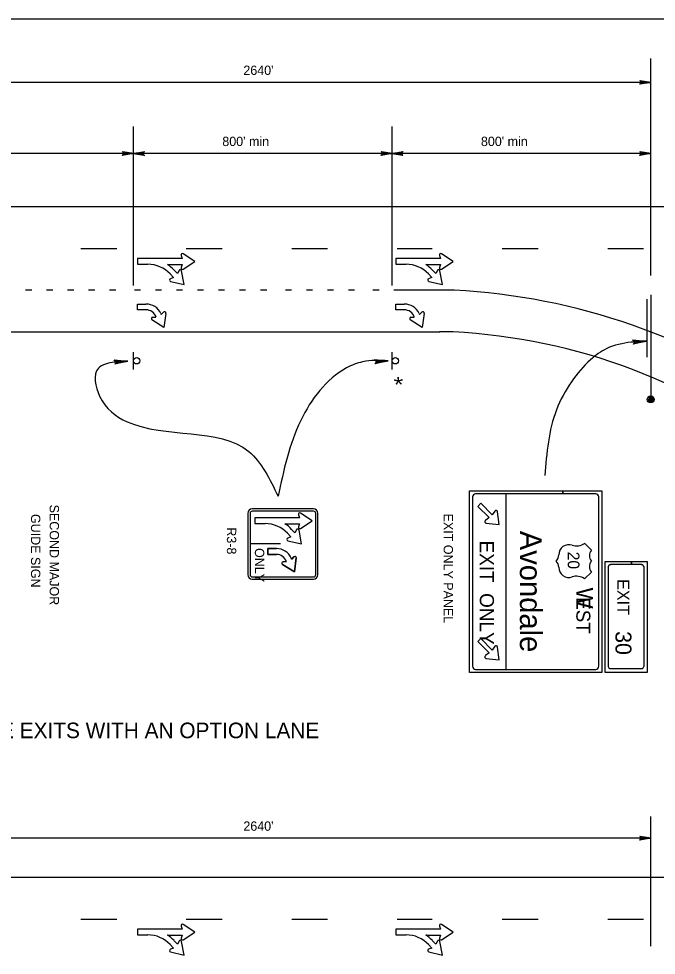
# Model space of a CAD drawing. Extents: x 644898 to 648326, y 298294 to 300670.
# Drawn here: x 645333.7 to 645538.5, y 298572.7 to 298873.5 of the extents above; entities that cross this region are included whole.
import ezdxf

# ---------------------------------------------------------------- set-up
doc = ezdxf.new("R2010")
doc.units = 0
doc.layers.add('1', color=7, linetype='Continuous')
doc.layers.add('2', color=7, linetype='Continuous')

msp = doc.modelspace()

# ---------------------------------------------------------------- linework, layer by layer
at = {"layer": '1'}
msp.add_line((644938.32, 298873.49), (645724.32, 298873.49), dxfattribs=at)
at = {"layer": '2'}
for p, q in [((645536.72, 298791.02), (645536.72, 298860.69)), ((645533.35, 298853.56), (645533.22, 298853.69)), ((645533.22, 298853.69), (645536.72, 298853.06)), ((645533.35, 298853.56), (645533.47, 298853.31)), ((645536.72, 298853.06), (645533.35, 298853.56)), ((645536.72, 298853.06), (645287.45, 298853.06)), ((645536.72, 298853.06), (645533.22, 298852.44)), ((645533.22, 298852.44), (645533.35, 298852.69)), ((645533.35, 298852.69), (645536.72, 298853.06)), ((645533.47, 298852.94), (645533.35, 298852.69)), ((645533.47, 298853.31), (645536.72, 298853.06)), ((645536.72, 298853.06), (645533.47, 298852.94)), ((645370.54, 298787.81), (645370.54, 298838.91)), ((645453.63, 298787.81), (645453.63, 298838.91)), ((645370.54, 298830.22), (645287.45, 298830.22)), ((645367.17, 298830.72), (645367.04, 298830.85)), ((645367.04, 298830.85), (645370.54, 298830.22)), ((645370.54, 298830.22), (645367.04, 298829.6)), ((645367.04, 298829.6), (645367.17, 298829.85)), ((645367.17, 298830.72), (645367.29, 298830.47)), ((645370.54, 298830.22), (645367.17, 298830.72)), ((645367.17, 298829.85), (645370.54, 298830.22)), ((645367.29, 298830.1), (645367.17, 298829.85)), ((645367.29, 298830.47), (645370.54, 298830.22)), ((645370.54, 298830.22), (645367.29, 298830.1)), ((645370.54, 298830.22), (645374.04, 298830.85)), ((645373.92, 298830.6), (645370.54, 298830.22)), ((645370.54, 298830.22), (645373.79, 298830.35)), ((645453.63, 298830.22), (645370.54, 298830.22)), ((645373.79, 298829.97), (645370.54, 298830.22)), ((645370.54, 298830.22), (645373.92, 298829.72)), ((645374.04, 298829.6), (645370.54, 298830.22)), ((645373.79, 298830.35), (645373.92, 298830.6)), ((645373.92, 298829.72), (645373.79, 298829.97)), ((645374.04, 298830.85), (645373.92, 298830.6)), ((645373.92, 298829.72), (645374.04, 298829.6)), ((645450.26, 298830.72), (645450.13, 298830.85)), ((645450.13, 298830.85), (645453.63, 298830.22)), ((645453.63, 298830.22), (645450.13, 298829.6)), ((645450.13, 298829.6), (645450.26, 298829.85)), ((645450.26, 298830.72), (645450.38, 298830.47)), ((645453.63, 298830.22), (645450.26, 298830.72)), ((645450.26, 298829.85), (645453.63, 298830.22)), ((645450.38, 298830.1), (645450.26, 298829.85)), ((645450.38, 298830.47), (645453.63, 298830.22)), ((645453.63, 298830.22), (645450.38, 298830.1)), ((645453.63, 298830.22), (645457.13, 298830.85)), ((645457.01, 298830.6), (645453.63, 298830.22)), ((645453.63, 298830.22), (645456.88, 298830.35)), ((645536.72, 298830.22), (645453.63, 298830.22)), ((645456.88, 298829.97), (645453.63, 298830.22)), ((645453.63, 298830.22), (645457.01, 298829.72)), ((645457.13, 298829.6), (645453.63, 298830.22)), ((645456.88, 298830.35), (645457.01, 298830.6)), ((645457.01, 298829.72), (645456.88, 298829.97)), ((645457.13, 298830.85), (645457.01, 298830.6)), ((645457.01, 298829.72), (645457.13, 298829.6)), ((645533.35, 298830.72), (645533.22, 298830.85)), ((645533.22, 298830.85), (645536.72, 298830.22)), ((645536.72, 298830.22), (645533.22, 298829.6)), ((645533.22, 298829.6), (645533.35, 298829.85)), ((645533.35, 298830.72), (645533.47, 298830.47)), ((645536.72, 298830.22), (645533.35, 298830.72)), ((645533.35, 298829.85), (645536.72, 298830.22)), ((645533.47, 298830.1), (645533.35, 298829.85)), ((645533.47, 298830.47), (645536.72, 298830.22)), ((645536.72, 298830.22), (645533.47, 298830.1)), ((645010.69, 298813.15), (645651.96, 298813.15)), ((645353.66, 298799.69), (645365.16, 298799.69)), ((645387.53, 298799.69), (645399.03, 298799.69)), ((645421.41, 298799.69), (645432.91, 298799.69)), ((645455.28, 298799.69), (645466.53, 298799.69)), ((645489.03, 298799.69), (645500.53, 298799.69)), ((645522.91, 298799.69), (645534.41, 298799.69)), ((645386.24, 298796.46), (645371.85, 298796.46)), ((645371.85, 298796.46), (645371.85, 298794.63)), ((645385.85, 298797.44), (645386.24, 298796.46)), ((645390.3, 298795.53), (645386.51, 298797.99)), ((645469.23, 298796.46), (645454.84, 298796.46)), ((645454.84, 298796.46), (645454.84, 298794.63)), ((645468.84, 298797.44), (645469.23, 298796.46)), ((645473.29, 298795.53), (645469.5, 298797.99)), ((645371.85, 298794.63), (645375.15, 298794.63)), ((645381.45, 298794.59), (645386.24, 298794.59)), ((645386.24, 298794.59), (645385.85, 298793.61)), ((645386.51, 298793.07), (645390.3, 298795.53)), ((645454.84, 298794.63), (645458.14, 298794.63)), ((645464.43, 298794.59), (645469.23, 298794.59)), ((645469.23, 298794.59), (645468.84, 298793.61)), ((645469.5, 298793.07), (645473.29, 298795.53)), ((645382.34, 298791.53), (645383.41, 298790.4)), ((645383.41, 298790.4), (645382.4, 298789.99)), ((645384.72, 298791.63), (645383.65, 298792.77)), ((645385.18, 298792.63), (645384.72, 298791.63)), ((645386.85, 298788.08), (645386.03, 298792.52)), ((645465.33, 298791.53), (645466.4, 298790.4)), ((645466.4, 298790.4), (645465.38, 298789.99)), ((645467.71, 298791.63), (645466.63, 298792.77)), ((645468.17, 298792.63), (645467.71, 298791.63)), ((645469.84, 298788.08), (645469.02, 298792.52)), ((645382.46, 298789.14), (645386.85, 298788.08)), ((645465.45, 298789.14), (645469.84, 298788.08)), ((645337.85, 298786.27), (645335.85, 298786.27)), ((645344.6, 298786.27), (645342.6, 298786.27)), ((645351.35, 298786.27), (645349.35, 298786.27)), ((645358.1, 298786.27), (645356.1, 298786.27)), ((645364.85, 298786.27), (645362.85, 298786.27)), ((645372.84, 298786.27), (645370.84, 298786.27)), ((645379.59, 298786.27), (645377.59, 298786.27)), ((645386.34, 298786.27), (645384.34, 298786.27)), ((645393.09, 298786.27), (645391.09, 298786.27)), ((645399.84, 298786.27), (645397.84, 298786.27)), ((645406.59, 298786.27), (645404.59, 298786.27)), ((645413.34, 298786.27), (645411.34, 298786.27)), ((645421.34, 298786.27), (645419.34, 298786.27)), ((645428.09, 298786.27), (645426.09, 298786.27)), ((645434.84, 298786.27), (645432.84, 298786.27)), ((645441.59, 298786.27), (645439.59, 298786.27)), ((645449.45, 298786.27), (645447.45, 298786.27)), ((645473.61, 298786.27), (645454.2, 298786.27)), ((645536.72, 298784.86), (645536.72, 298751.17)), ((645535.6, 298764.78), (645535.6, 298783.37)), ((645010.69, 298772.9), (645442.59, 298772.9)), ((645442.59, 298772.9), (645454.2, 298772.9)), ((645454.2, 298772.9), (645468.92, 298772.9)), ((645370.54, 298760.83), (645370.54, 298766.45)), ((645453.63, 298760.83), (645453.63, 298766.45)), ((645537.47, 298751.42), (645535.85, 298751.04)), ((645536.6, 298750.42), (645535.85, 298751.29)), ((645535.85, 298751.29), (645537.22, 298750.42)), ((645537.22, 298751.92), (645535.97, 298751.54)), ((645535.97, 298751.54), (645537.47, 298751.42)), ((645536.1, 298751.92), (645537.22, 298751.92)), ((645537.22, 298750.42), (645536.6, 298752.17)), ((645536.6, 298752.17), (645537.72, 298751.04)), ((645537.72, 298751.04), (645537.22, 298752.04)), ((645535.85, 298751.04), (645537.72, 298751.04)), ((645537.72, 298751.04), (645535.97, 298750.67)), ((645535.97, 298750.67), (645537.47, 298750.67)), ((645537.47, 298750.67), (645536.6, 298750.42)), ((645536.72, 298751.17), (645536.72, 298751.17)), ((645478.45, 298663.53), (645478.45, 298721.9)), ((645478.45, 298721.9), (645508.47, 298721.9)), ((645508.47, 298720.9), (645508.47, 298721.9)), ((645508.47, 298721.9), (645521.07, 298721.9)), ((645508.47, 298721.9), (645508.47, 298720.9)), ((645521.07, 298721.9), (645521.07, 298663.53)), ((645479.45, 298719.9), (645479.45, 298665.53)), ((645520.07, 298665.53), (645520.07, 298719.9)), ((645482.18, 298717.88), (645481.18, 298716.88)), ((645481.18, 298716.88), (645484.8, 298713.25)), ((645485.8, 298714.19), (645482.18, 298717.88)), ((645486.61, 298715.38), (645485.8, 298714.19)), ((645423.94, 298713.18), (645409.55, 298713.18)), ((645409.55, 298713.18), (645409.55, 298711.34)), ((645423.55, 298714.16), (645423.94, 298713.18)), ((645428, 298712.24), (645424.21, 298714.7)), ((645424.21, 298709.78), (645428, 298712.24)), ((645484.8, 298713.25), (645483.61, 298712.38)), ((645488.05, 298711), (645487.55, 298715.13)), ((645409.55, 298711.34), (645412.85, 298711.34)), ((645419.14, 298711.3), (645423.94, 298711.3)), ((645422.42, 298708.35), (645421.35, 298709.48)), ((645422.88, 298709.34), (645422.42, 298708.35)), ((645423.94, 298711.3), (645423.55, 298710.32)), ((645424.55, 298704.79), (645423.73, 298709.23)), ((645483.8, 298711.5), (645488.05, 298711)), ((645420.04, 298708.24), (645421.11, 298707.11)), ((645421.11, 298707.11), (645420.1, 298706.7)), ((645420.16, 298705.85), (645424.55, 298704.79)), ((645515.45, 298705.06), (645517.7, 298702.81)), ((645507.2, 298701.31), (645507.2, 298701.31)), ((645507.2, 298697.31), (645507.2, 298697.31)), ((645511.95, 298699.31), (645511.95, 298699.31)), ((645511.95, 298699.31), (645511.95, 298699.31)), ((645511.95, 298699.31), (645511.95, 298699.31)), ((645511.95, 298699.31), (645511.95, 298699.31)), ((645511.95, 298699.31), (645511.95, 298699.31)), ((645511.95, 298699.31), (645511.95, 298699.31)), ((645522.07, 298663.53), (645522.07, 298699.15)), ((645522.07, 298699.15), (645530.53, 298699.15)), ((645523.07, 298697.53), (645523.07, 298665.4)), ((645530.53, 298698.15), (645523.82, 298698.15)), ((645530.53, 298698.15), (645530.53, 298699.15)), ((645530.53, 298699.15), (645535.57, 298699.15)), ((645530.53, 298699.15), (645530.53, 298698.15)), ((645533.82, 298698.15), (645530.53, 298698.15)), ((645534.57, 298665.4), (645534.57, 298697.53)), ((645535.57, 298699.15), (645535.57, 298663.53)), ((645509.7, 298697.06), (645509.7, 298697.06)), ((645517.7, 298695.69), (645515.45, 298693.56)), ((645510.45, 298694.06), (645510.45, 298694.06)), ((645482.18, 298674.43), (645481.18, 298673.43)), ((645481.18, 298673.43), (645484.8, 298669.8)), ((645485.8, 298670.74), (645482.18, 298674.43)), ((645486.61, 298671.93), (645485.8, 298670.74)), ((645488.05, 298667.55), (645487.55, 298671.68)), ((645484.8, 298669.8), (645483.61, 298668.93)), ((645483.8, 298668.05), (645488.05, 298667.55)), ((645480.45, 298664.53), (645519.07, 298664.53)), ((645523.82, 298664.78), (645533.82, 298664.78)), ((645521.07, 298663.53), (645478.45, 298663.53)), ((645535.57, 298663.53), (645522.07, 298663.53)), ((645536.72, 298575.63), (645536.72, 298617.3)), ((645536.72, 298610.3), (645287.45, 298610.3)), ((645533.35, 298610.8), (645533.22, 298610.93)), ((645533.22, 298610.93), (645536.72, 298610.3)), ((645536.72, 298610.3), (645533.22, 298609.68)), ((645533.22, 298609.68), (645533.35, 298609.93)), ((645533.35, 298610.8), (645533.47, 298610.55)), ((645536.72, 298610.3), (645533.35, 298610.8)), ((645533.35, 298609.93), (645536.72, 298610.3)), ((645533.47, 298610.18), (645533.35, 298609.93)), ((645533.47, 298610.55), (645536.72, 298610.3)), ((645536.72, 298610.3), (645533.47, 298610.18)), ((645010.69, 298597.76), (645651.96, 298597.76)), ((645353.66, 298584.3), (645365.16, 298584.3)), ((645387.53, 298584.3), (645399.03, 298584.3)), ((645421.41, 298584.3), (645432.91, 298584.3)), ((645455.28, 298584.3), (645466.53, 298584.3)), ((645489.03, 298584.3), (645500.53, 298584.3)), ((645522.91, 298584.3), (645534.41, 298584.3)), ((645386.24, 298581.08), (645371.85, 298581.08)), ((645371.85, 298581.08), (645371.85, 298579.24)), ((645385.85, 298582.06), (645386.24, 298581.08)), ((645390.3, 298580.14), (645386.51, 298582.6)), ((645386.51, 298577.68), (645390.3, 298580.14)), ((645469.23, 298581.08), (645454.84, 298581.08)), ((645454.84, 298581.08), (645454.84, 298579.24)), ((645468.84, 298582.06), (645469.23, 298581.08)), ((645473.29, 298580.14), (645469.5, 298582.6)), ((645469.5, 298577.68), (645473.29, 298580.14)), ((645371.85, 298579.24), (645375.15, 298579.24)), ((645381.45, 298579.2), (645386.24, 298579.2)), ((645384.72, 298576.25), (645383.65, 298577.38)), ((645385.18, 298577.24), (645384.72, 298576.25)), ((645386.24, 298579.2), (645385.85, 298578.22)), ((645386.85, 298572.69), (645386.03, 298577.13)), ((645454.84, 298579.24), (645458.14, 298579.24)), ((645464.43, 298579.2), (645469.23, 298579.2)), ((645467.71, 298576.25), (645466.63, 298577.38)), ((645468.17, 298577.24), (645467.71, 298576.25)), ((645469.23, 298579.2), (645468.84, 298578.22)), ((645469.84, 298572.69), (645469.02, 298577.13)), ((645382.34, 298576.15), (645383.41, 298575.01)), ((645383.41, 298575.01), (645382.4, 298574.61)), ((645382.46, 298573.75), (645386.85, 298572.69)), ((645465.33, 298576.15), (645466.4, 298575.01)), ((645466.4, 298575.01), (645465.38, 298574.61)), ((645465.45, 298573.75), (645469.84, 298572.69))]:
    msp.add_line(p, q, dxfattribs=at)
for points in [[(645374.57, 298780), (645371.85, 298780), (645371.85, 298781.87), (645374.57, 298781.87)], [(645457.56, 298780), (645454.84, 298780), (645454.84, 298781.87), (645457.56, 298781.87)], [(645380.96, 298778.84), (645380.34, 298774.37), (645376.5, 298776.77)], [(645379.35, 298778.8), (645379.49, 298778.48), (645380.19, 298779.21)], [(645463.95, 298778.84), (645463.32, 298774.37), (645459.49, 298776.77)], [(645462.33, 298778.8), (645462.48, 298778.48), (645463.18, 298779.21)], [(645376.72, 298777.59), (645377.78, 298777.66)], [(645459.7, 298777.59), (645460.77, 298777.66)], [(645531.16, 298770.09), (645531.29, 298769.96), (645535.29, 298769.96), (645531.16, 298770.09), (645530.91, 298770.34), (645535.29, 298769.96), (645531.41, 298769.46), (645531.29, 298769.21), (645535.29, 298769.96), (645531.16, 298768.96), (645531.29, 298769.21)], [(645364.6, 298763.65), (645364.73, 298763.52), (645368.73, 298763.52), (645364.6, 298763.65), (645364.35, 298763.9), (645368.73, 298763.52), (645364.85, 298763.02), (645364.73, 298762.77), (645368.73, 298763.52), (645364.6, 298762.52), (645364.73, 298762.77)], [(645448.2, 298763.76), (645448.33, 298763.63), (645452.33, 298763.63), (645448.2, 298763.76), (645447.95, 298764.01), (645452.33, 298763.63), (645448.45, 298763.13), (645448.33, 298762.88), (645452.33, 298763.63), (645448.2, 298762.63), (645448.33, 298762.88)], [(645508.47, 298720.9), (645480.45, 298720.9)], [(645490.2, 298720.9), (645490.2, 298664.53)], [(645519.07, 298720.9), (645508.47, 298720.9)], [(645428.39, 298716.04), (645408.71, 298716.04)], [(645428.39, 298715.33), (645408.71, 298715.33)], [(645407.3, 298714.63), (645407.3, 298694.94)], [(645408, 298714.63), (645408, 298694.94)], [(645423.55, 298714.16), (645423.94, 298713.18), (645409.55, 298713.18), (645409.55, 298711.34)], [(645424.21, 298709.78), (645428, 298712.24), (645424.21, 298714.7)], [(645429.1, 298694.94), (645429.1, 298714.63)], [(645429.8, 298694.94), (645429.8, 298714.63)], [(645409.55, 298711.34), (645412.85, 298711.34)], [(645419.14, 298711.3), (645423.94, 298711.3), (645423.55, 298710.32)], [(645420.16, 298705.85), (645424.55, 298704.79), (645423.73, 298709.23)], [(645422.88, 298709.34), (645422.42, 298708.35), (645421.35, 298709.48)], [(645420.04, 298708.24), (645421.11, 298707.11), (645420.1, 298706.7)], [(645417.8, 298704.79), (645408, 298704.79)], [(645416.48, 298701.46), (645413.76, 298701.46), (645413.76, 298703.33), (645416.48, 298703.33)], [(645413.76, 298703.33), (645413.76, 298701.46), (645416.48, 298701.46)], [(645416.48, 298703.33), (645413.76, 298703.33)], [(645422.87, 298700.31), (645422.25, 298695.83), (645418.42, 298698.23)], [(645418.42, 298698.23), (645422.25, 298695.83), (645422.87, 298700.31)], [(645421.26, 298700.26), (645421.4, 298699.94), (645422.1, 298700.68)], [(645422.1, 298700.68), (645421.4, 298699.94), (645421.26, 298700.26)], [(645418.63, 298699.06), (645419.69, 298699.12)], [(645419.69, 298699.12), (645418.63, 298699.06)], [(645408.71, 298694.24), (645428.39, 298694.24)], [(645408.71, 298693.54), (645428.39, 298693.54)]]:
    msp.add_lwpolyline(points, dxfattribs=at)
for centre, radius in [((645371.58, 298763.64), 1.03), ((645454.67, 298763.64), 1.03), ((645536.71, 298751.23), 1.12)]:
    msp.add_circle(centre, radius, dxfattribs=at)
for centre, radius, start, end in [((645386.27, 298797.61), 0.448, 57.025, 201.6038), ((645469.25, 298797.61), 0.448, 57.025, 201.6038), ((645375.15, 298784.73), 9.9, 43.4316, 90), ((645375.15, 298784.73), 11.7, 43.4316, 57.4528), ((645386.27, 298793.44), 0.448, 158.3962, 302.975), ((645458.14, 298784.73), 9.9, 43.4316, 90), ((645458.14, 298784.73), 11.7, 43.4316, 57.4528), ((645469.25, 298793.44), 0.448, 158.3962, 302.975), ((645385.59, 298792.44), 0.448, 10.4566, 155.0355), ((645468.58, 298792.44), 0.448, 10.4566, 155.0355), ((645382.56, 298789.57), 0.448, 111.8278, 256.4066), ((645465.55, 298789.57), 0.448, 111.8278, 256.4066), ((645463.66, 298583.71), 202.81, 54.115, 87.1891), ((645374.57, 298776.62), 5.25, 24.5121, 90), ((645457.56, 298776.62), 5.25, 24.5121, 90), ((645374.57, 298776.62), 3.38, 17.8867, 90), ((645380.52, 298778.91), 0.448, 352.025, 136.6038), ((645457.56, 298776.62), 3.38, 17.8867, 90), ((645463.51, 298778.91), 0.448, 352.025, 136.6038), ((645376.74, 298777.15), 0.448, 93.3962, 237.975), ((645459.73, 298777.15), 0.448, 93.3962, 237.975), ((645471.38, 298171.59), 601.31, 89.8236, 90.23471), ((645463.66, 298583.71), 189.43, 51.3209, 87.1047), ((645480.45, 298719.9), 1, 90, 180), ((645519.07, 298719.9), 1, 360, 90), ((645408.71, 298714.63), 1.41, 90, 180), ((645408.71, 298714.63), 0.703, 90, 180), ((645428.39, 298714.63), 1.41, 360, 90), ((645428.39, 298714.63), 0.703, 360, 90), ((645487.05, 298715.08), 0.489, 4.8565, 145.522), ((645423.97, 298714.32), 0.448, 57.025, 201.6038), ((645423.97, 298714.32), 0.448, 57.025, 201.6038), ((645483.9, 298711.96), 0.489, 123.2449, 267.1516), ((645412.85, 298701.44), 9.9, 43.4316, 90), ((645412.85, 298701.44), 9.9, 43.4316, 90), ((645412.85, 298701.44), 11.7, 43.4316, 57.4528), ((645412.85, 298701.44), 11.7, 43.4316, 57.4528), ((645423.29, 298709.15), 0.448, 10.4566, 155.0355), ((645423.29, 298709.15), 0.448, 10.4566, 155.0355), ((645423.97, 298710.16), 0.448, 158.3962, 302.975), ((645423.97, 298710.16), 0.448, 158.3962, 302.975), ((645420.26, 298706.29), 0.448, 111.8278, 256.4066), ((645420.26, 298706.29), 0.448, 111.8278, 256.4066), ((645416.48, 298698.08), 5.25, 24.5121, 90), ((645416.48, 298698.08), 5.25, 24.5121, 90), ((645510.44, 298701.31), 3.26, 71.452, 179.9953), ((645512.89, 298708.73), 4.55, 251.8289, 304.5747), ((645416.48, 298698.08), 3.38, 17.8867, 90), ((645416.48, 298698.08), 3.38, 17.8867, 90), ((645422.43, 298700.37), 0.448, 352.025, 136.6038), ((645422.43, 298700.37), 0.448, 352.025, 136.6038), ((645504.42, 298701.31), 2.76, 313.7275, 0), ((645519.99, 298701.06), 2.93, 143.136, 216.864), ((645418.65, 298698.61), 0.448, 93.3962, 237.975), ((645418.65, 298698.61), 0.448, 93.3962, 237.975), ((645504.42, 298697.3), 2.76, 0, 46.2725), ((645510.44, 298697.3), 3.26, 180.0047, 288.548), ((645519.99, 298697.55), 2.93, 143.136, 216.864), ((645408.71, 298694.94), 1.41, 180, 270), ((645408.71, 298694.94), 0.703, 180, 270), ((645428.39, 298694.94), 1.41, 270, 360), ((645428.39, 298694.94), 0.703, 270, 360), ((645512.89, 298689.88), 4.55, 55.4253, 108.1711), ((645487.05, 298671.63), 0.489, 4.8565, 145.522), ((645483.9, 298668.51), 0.489, 123.2449, 267.1516), ((645480.45, 298665.53), 1, 180, 270), ((645519.07, 298665.53), 1, 270, 0), ((645386.27, 298582.22), 0.448, 57.025, 201.6038), ((645469.25, 298582.22), 0.448, 57.025, 201.6038), ((645375.15, 298569.34), 9.9, 43.4316, 90), ((645375.15, 298569.34), 11.7, 43.4316, 57.4528), ((645385.59, 298577.05), 0.448, 10.4566, 155.0355), ((645386.27, 298578.06), 0.448, 158.3962, 302.975), ((645458.14, 298569.34), 9.9, 43.4316, 90), ((645458.14, 298569.34), 11.7, 43.4316, 57.4528), ((645468.58, 298577.05), 0.448, 10.4566, 155.0355), ((645469.25, 298578.06), 0.448, 158.3962, 302.975), ((645382.56, 298574.19), 0.448, 111.8278, 256.4066), ((645465.55, 298574.19), 0.448, 111.8278, 256.4066)]:
    msp.add_arc(centre, radius, start, end, dxfattribs=at)
for centre, major_axis, start_param, end_param in [((645523.87, 298697.47), (-0.792, 0), 4.712389, 6.283185), ((645533.72, 298697.47), (-0.792, 0), 3.141593, 4.712389), ((645523.87, 298665.44), (0.792, 0), 3.141593, 4.712389), ((645533.72, 298665.44), (0.792, 0), 4.712389, 6.283185)]:
    msp.add_ellipse(centre, major_axis=major_axis, ratio=0.827467, start_param=start_param, end_param=end_param, dxfattribs=at)
for points in [[(645535.29, 298769.96), (645530.41, 298769.59), (645522.61, 298767.55), (645517.38, 298763.95), (645511.28, 298756.91), (645506.44, 298747.89), (645502.7, 298726.77)], [(645366.64, 298763.36), (645364.4, 298763.18), (645359.29, 298761.23), (645359.67, 298752.27), (645368.51, 298744.05), (645407.6, 298734.49), (645417.02, 298720.13)], [(645452.33, 298763.63), (645444.15, 298763.29), (645439.04, 298761.34), (645424.28, 298744.44), (645417.02, 298720.13)]]:
    msp.add_spline(points, degree=3, dxfattribs=at)

# ---------------------------------------------------------------- texts
for s, height, rotation, p in [("2640'", 3, 360, (645405.85, 298855.44)), ("800' min ", 3, 360, (645399.09, 298832.6)), ("800' min ", 3, 360, (645482.18, 298832.6)), ('*', 5.42, 75.7789, (645459.19, 298754.78)), ('SECOND MAJOR', 3, 270, (645343.62, 298717.43)), ('GUIDE SIGN', 3, 270, (645337.62, 298714.43)), ('EXIT ONLY PANEL', 3, 270, (645470.19, 298714.56)), ('R3-8', 3, 270, (645400.56, 298710.14)), ('Avondale', 7, 269.9998, (645494.7, 298709.03)), ('ONLY', 3, 270, (645409.55, 298703.48)), ('EXIT  ONLY', 4.546, 270, (645481.82, 298705.9)), ('20', 3.75, 270, (645510.07, 298702.31)), ('EXIT', 3.875, 270, (645525.97, 298693.51)), ('W', 5.38, 270, (645512.82, 298690.81)), ('EST', 4.5, 270, (645512.82, 298687.69)), ('30', 5.125, 270, (645525.4, 298676.79)), ("2640'", 3, 360, (645405.85, 298612.68))]:
    msp.add_text(s, height=height, rotation=rotation, dxfattribs=at).set_placement(p)
msp.add_text('INTERMEDIATE & MINOR INTERCHANGE MULTI-LANE EXITS WITH AN OPTION LANE', height=5, dxfattribs=at).set_placement((645159.79, 298642.42))

doc.saveas('drawing.dxf')
